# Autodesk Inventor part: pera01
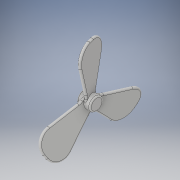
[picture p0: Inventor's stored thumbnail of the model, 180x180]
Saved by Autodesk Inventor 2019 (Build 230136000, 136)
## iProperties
Created: 2020-08
Part Number: pera01
Material: 一般
Document SubType Name: Modeling
Designer: kikut
Density: 1 g/cm^3
Appearance: 既定
Author: kikut
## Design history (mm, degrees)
sketch "スケッチ3"
  geometry: L1 (0.005, -0.009)-(-0.001, 0.01); L2 (-0.001, 0.01)-(-0.005, 0.009); L3 (-0.005, 0.009)-(0.001, -0.01); L4 (0.001, -0.01)-(0.005, -0.009); L5 (0.005, -0.009)-(-0.005, 0.009); L6 (-0.001, 0.01)-(0.001, -0.01); L7 (0, -0.014)-(0, 0.014) reference; 3 further points
  constraints: 12 end point, 3 midpoint, 2 parallel, 1 coincident, 1 perpendicular
  dimensions: "d8" = 0.02 distance of L1.start L1.end; "d9" = 15 deg angle of L7 L1; "d19" = 0.004 distance of L3.end L1.start
extrude "押し出し1" new body sketch "スケッチ3" distance "d10" = 0.079; taper "d11" = 0 deg
sketch "スケッチ6"
  geometry: L1 (-0.02, 0)-(-0.02, 0.079) reference; L2 (-0.02, 0.01)-(-0.04, 0.079); L3 (-0.04, 0.079)-(0.02, 0.079); L4 (0.02, 0.079)-(0, 0.01); L5 (0, 0)-(0, 0.079) reference; L6 (-0.02, 0.01)-(0, 0.01); L7 (-0.02, 0)-(0, 0) reference; 1 further point
  constraints: 8 end point, 2 perpendicular, 2 point on line
  dimensions: "d20" = 0.06 distance of L2.end L3.end; "d21" = 0.01 distance between parallel lines of L7 L6; "d22" = 0.02 distance from line of L1 L2.end
extrude "押し出し3" join sketch "スケッチ6" distance "d23" = 0.004; taper "d24" = 0 deg
fillet "フィレット2" dims "d25" = 0.02
fillet "フィレット3" dims "d26" = 0.02
pattern_circular "円形状パターン2" dims "d28" = 360 deg
sketch "スケッチ7"
  geometry: L1 (-0.008, -0.005)-(0, 0) reference; C1 r 0.01 at (0, 0)
  constraints: 1 centre point, 1 coincident
  dimensions: "d30" = 0.02 diameter of C1
extrude "押し出し4" join sketch "スケッチ7" stored distance "d31" = 0.02; taper "d32" = 0 deg
fillet "フィレット4" dims "d33" = 0.002
node "ソリッド1"
